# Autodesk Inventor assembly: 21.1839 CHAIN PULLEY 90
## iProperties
Created: 2007-05
Part Number: 21.1839 CHAIN PULLEY 90
Document SubType Name: Assembly
Designer: Andy Moles
Mass: 702.246 g
Surface Area: 1402.98 cm^2
Volume: 226.39 cm^3
Density: 3.10193 g/cm^3
Author: Andy Moles
